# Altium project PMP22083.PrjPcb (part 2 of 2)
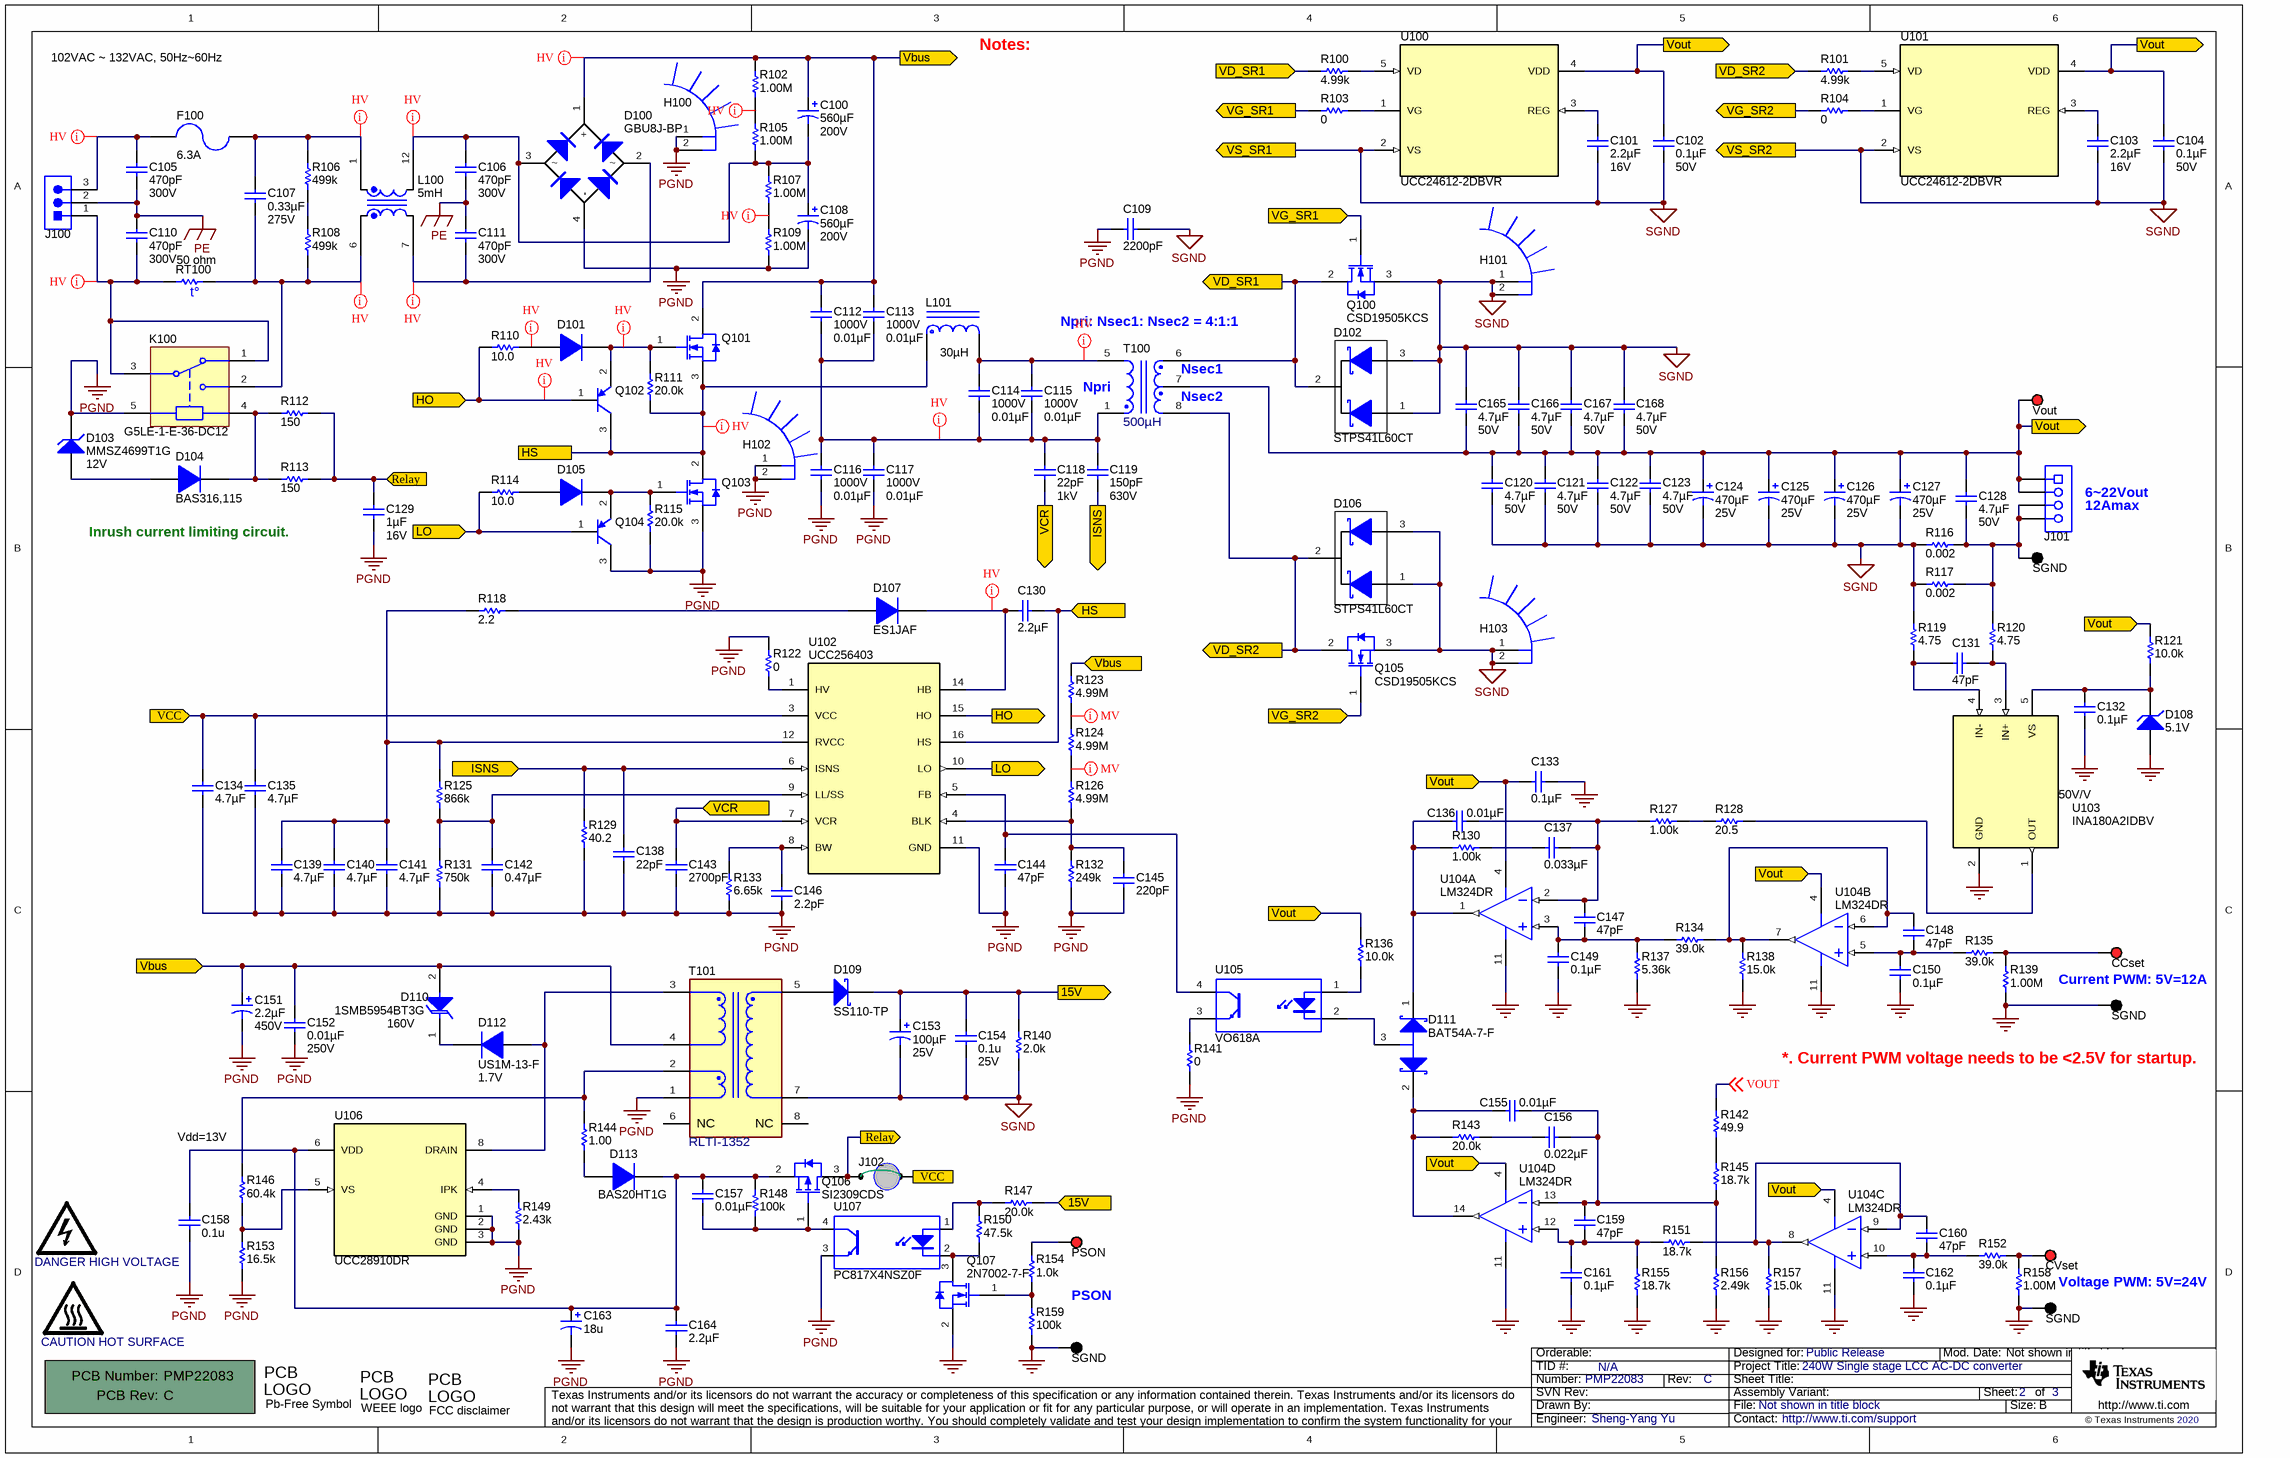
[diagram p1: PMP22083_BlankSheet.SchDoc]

## Sheet PMP22083_BlankSheet.SchDoc (continued)

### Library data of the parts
!PCB100 = CMP-0003618-2: Manufacturer: Any; PartNumber: PMP22083
C100 C108 = CMP-0010098-2: CAP, AL, 560 uF, 200 V, +/- 20%, TH; Manufacturer: Nichicon; PartNumber: LGR2D561MELZ45; TaMin_C: -25°C; Polarized: Y; SizeAreaWB_mm2: 576; Value1: Unknown; U/M: EA; Value: 560uF; TaMax_C: 85°C; SizeZ_mm: 32; SizeX_mm: 22; SizeArea_mm2: 484; CompType: Capacitor; AEC Qualified: N; AEC Category: Q200
C101 C103 = 885012106018: CAP, CERM, 2.2 µF, 16 V,+/- 20%, X5R, 0603; Manufacturer: Wurth Elektronik; Polarized: N; CompType: Capacitor; Value: 2.2uF; U/M: EA; Cap_F: 0.0000022; Tolerance_%: 20; VDC_V: 16; TaMin_C: -55; TaMax_C: 85; SizeArea_mm2: 1.28; SizeAreaWB_mm2: 4.68; SizeX_mm: 1.6; SizeY_mm: 0.8; SizeZ_mm: 1; AEC Category: Q200; Green_Lifecycle: Not Set; Green_REACh: Incomplete
C102 C104 = 885012206095: CAP, CERM, 0.1 µF, 50 V,+/- 10%, X7R, 0603; Manufacturer: Wurth Elektronik; Polarized: N; CompType: Capacitor; Value: 0.1uF; U/M: EA; Cap_F: 0.0000001; Tolerance_%: 10; VDC_V: 50; TaMin_C: -55; TaMax_C: 125; SizeArea_mm2: 1.28; SizeAreaWB_mm2: 4.68; SizeX_mm: 1.6; SizeY_mm: 0.8; SizeZ_mm: 1; AEC Category: Q200; Green_Lifecycle: Active; Green_REACh: Passed
C105 C106 C110 C111 = VY2471K29Y5SS63V7: CAP, CERM, 470pF, 300V, +/-10%, VY2, 5x7.5 mm; Manufacturer: Vishay-Bccomponents; Polarized: N; CompType: Capacitor; U/M: EA; Cap_F: 0.00000000047; Tolerance_%: 10; Value1: Unknown; VDC_V: 300; TaMin_C: -40; TaMax_C: 125; Cap_Case: Disk, 5x7.5 mm
C107 = ECQ-U2A334ML: CAP, Film, 0.33uF, 275V, +/-20%, TH; Manufacturer: Panasonic; Polarized: N; CompType: Capacitor; U/M: EA; Cap_F: 0.00000033; Tolerance_%: 20; Value1: Unknown; VDC_V: 275; TaMin_C: -40; TaMax_C: 100; Cap_Case: Radial,17.5x17.5x9.5mm
C109 = AY2222M35Y5US63L7: CAP, CERM, 2200 pF, 300 V, +/- 20%, Y5U, AEC-Q200 Grade 1, D9.5xT5mm; Manufacturer: Vishay-Bccomponents; Polarized: N; CompType: Capacitor; Value: 2200pF; U/M: EA; Cap_F: 0.0000000022; Tolerance_%: 20; Value1: Unknown; VDC_V: 300; Value2: 300V; TaMin_C: -55; TaMax_C: 125; Cap_Case: 9.5x5mm; SizeArea_mm2: 47.5; SizeAreaWB_mm2: 80.5; SizeX_mm: 9.5; SizeY_mm: 5; SizeZ_mm: 14.5; AEC Category: Q200; AEC Qualified: Y; AEC Grade: 1
C112-C117 = CMP-0074802-2: CAP FILM 10000PF 5% 1KVDC RADIAL; Manufacturer: TDK; TaMin_C: -55°C; Polarized: N; SizeAreaWB_mm2: 120.0; Value: 0.01uF; TaMax_C: 105°C; VAC: 400; SizeZ_mm: 12.0; SizeX_mm: 13.0; SizeY_mm: 6.0; Cap_Case: 13x6x12mm; SizeArea_mm2: 78.0; CompType: Capacitor; Cap_F: 22nF; AEC Category: Q200
C118 = VJ1206A220JXGAT5Z: CAP, CERM, 22 pF, 1000 V,+/- 5%, C0G/NP0, 1206; Manufacturer: Vishay-Vitramon; Polarized: N; CompType: Capacitor; Value: 22pF; U/M: EA; Cap_F: 0.000000000022; Tolerance_%: 5; VDC_V: 1000; TaMin_C: -55; TaMax_C: 125; SizeArea_mm2: 5.12; SizeAreaWB_mm2: 10.92; SizeX_mm: 3.2; SizeY_mm: 1.6; SizeZ_mm: 1.35; AEC Category: Q200
C119 = GRM31A5C2J151JW01D: CAP, CERM, 150 pF, 630 V, +/- 5%, C0G/NP0, 1206; Manufacturer: MuRata; Polarized: N; CompType: Capacitor; Value: 150pF; U/M: EA; Cap_F: 0.00000000015; Tolerance_%: 5; Value1: Unknown; VDC_V: 630; TaMin_C: -55; TaMax_C: 125; SizeArea_mm2: 5.12; SizeAreaWB_mm2: 10.92; SizeX_mm: 3.2; SizeY_mm: 1.6; SizeZ_mm: 1.35; AEC Category: Q200
C120-C123 C128 C165-C168 = UMK316AB7475KL-T: CAP, CERM, 4.7 µF, 50 V,+/- 10%, X7R, 1206; Manufacturer: Taiyo Yuden; Polarized: N; CompType: Capacitor; Value: 4.7uF; U/M: EA; Cap_F: 0.0000047; Tolerance_%: 10; VDC_V: 50; TaMin_C: -55; TaMax_C: 125; Cap_Case: 1206; SizeArea_mm2: 5.12; SizeAreaWB_mm2: 10.92; SizeX_mm: 3.2; SizeY_mm: 1.6; SizeZ_mm: 1.9; AEC Category: Q200; Green_Lifecycle: Active; Green_REACh: Passed
C124-C127 = EEU-FR1V681: CAP ALUM POLY 470UF 20% 25V T/H; Manufacturer: Panasonic; Polarized: Y; CompType: Capacitor; U/M: EA; Tolerance_%: 20; VDC_V: 25; IRMS_A: 2.47; TaMin_C: -40; TaMax_C: 105; SizeAreaWB_mm2: 144; SizeArea_mm2: 100; SizeX_mm: 10; SizeZ_mm: 22; AEC Category: Q200; AEC Qualified: N
C129 = 0805YD105KAT2A: CAP, CERM, 1uF, 16V, +/-10%, X5R, 0805; Manufacturer: AVX; Polarized: N; CompType: Capacitor; U/M: EA; Cap_F: 0.000001; Tolerance_%: 10; ESR_Ohm: 0.012; Value1: 0.012 ohm; VDC_V: 16; TaMin_C: -55; TaMax_C: 85; Cap_Case: 0805
C130 = C1206C225K4RACTU: CAP, CERM, 2.2 µF, 16 V, +/- 10%, X7R, 1206; Manufacturer: Kemet; Polarized: N; CompType: Capacitor; Value: 2.2uF; U/M: EA; Cap_F: 0.0000022; Tolerance_%: 10; ESR_ohm: 0.009; Value1: 0.009 ohm; VDC_V: 16; Value2: 16V; IRMS_A: 4.46; TaMin_C: -55; TaMax_C: 125; AEC Category: Q200; SizeArea_mm2: 5.12; SizeAreaWB_mm2: 10.92; SizeX_mm: 3.2; SizeY_mm: 1.6; SizeZ_mm: 1.35
C131 = C0603C470J5GACTU: CAP, CERM, 47 pF, 50 V, +/- 5%, C0G/NP0, 0603; Manufacturer: Kemet; Polarized: N; CompType: Capacitor; Value: 47pF; U/M: EA; Cap_F: 0.000000000047; Tolerance_%: 5; Value1: Unknown; VDC_V: 50; Value2: 50V; TaMin_C: -55; TaMax_C: 125; SizeArea_mm2: 1.28; SizeAreaWB_mm2: 4.68; SizeX_mm: 1.6; SizeY_mm: 0.8; SizeZ_mm: 1; AEC Category: Q200
C132 = GRM155R61E104KA87D: CAP, CERM, 0.1 µF, 25 V, +/- 10%, X5R, 0402; Manufacturer: MuRata; Polarized: N; CompType: Capacitor; Value: 0.1uF; U/M: EA; Cap_F: 0.0000001; Tolerance_%: 10; Value1: Unknown; VDC_V: 25; Value2: 25V; TaMin_C: -55; TaMax_C: 85
C133 = C1206C104K5RACTU: CAP, CERM, 0.1 µF, 50 V, +/- 10%, X7R, 1206; Manufacturer: Kemet; Polarized: N; CompType: Capacitor; Value: 0.1uF; U/M: EA; Cap_F: 0.0000001; Tolerance_%: 10; ESR_ohm: 0.059; Value1: 0.059 ohm; VDC_V: 50; Value2: 50V; IRMS_A: 1.2; TaMin_C: -55; TaMax_C: 125; SizeArea_mm2: 5.12; SizeAreaWB_mm2: 10.92; SizeX_mm: 3.2; SizeY_mm: 1.6; SizeZ_mm: 1.35; AEC Category: Q200
C134 C135 C139-C141 = GRM188R61C475KAAJ: CAP, CERM, 4.7 µF, 16 V, +/- 10%, X5R, 0603; Manufacturer: MuRata; Polarized: N; CompType: Capacitor; Value: 4.7uF; U/M: EA; Cap_F: 0.0000047; Tolerance_%: 10; Value1: Unknown; VDC_V: 16; Value2: 16V; TaMin_C: -55; TaMax_C: 85; AEC Category: Q200
C136 C155 = GRM155R71H103KA88D: CAP, CERM, 0.01 µF, 50 V, +/- 10%, X7R, 0402; Manufacturer: MuRata; Polarized: N; CompType: Capacitor; Value: 0.01uF; U/M: EA; Cap_F: 0.00000001; Tolerance_%: 10; Value1: Unknown; VDC_V: 50; Value2: 50V; TaMin_C: -55; TaMax_C: 125
C137 = GRM155R61C333KA01D: CAP, CERM, 0.033 µF, 16 V,+/- 10%, X5R, 0402; Manufacturer: MuRata; Polarized: N; CompType: Capacitor; Value: 0.033uF; U/M: EA; Cap_F: 0.000000033; Tolerance_%: 10; VDC_V: 16; Value2: 16V; TaMin_C: -55; TaMax_C: 85; SizeArea_mm2: 0.5; SizeAreaWB_mm2: 3; SizeX_mm: 1; SizeZ_mm: 0.6; AEC Category: Q200; Green_Lifecycle: Active; Green_REACh: Passed
C138 = 06035A220JAT2A: CAP, CERM, 22 pF, 50 V,+/- 5%, C0G/NP0, 0603; Manufacturer: AVX; Polarized: N; CompType: Capacitor; Value: 22pF; U/M: EA; Cap_F: 0.000000000022; Tolerance_%: 5; ESR_ohm: 0.259; Value1: 0.259 ohm; VDC_V: 50; Value2: 50V; TaMin_C: -55; TaMax_C: 125; SizeArea_mm2: 1.28; SizeAreaWB_mm2: 4.68; SizeX_mm: 1.6; SizeY_mm: 0.8; SizeZ_mm: 1; AEC Category: Q200; Green_Lifecycle: Active; Green_REACh: Passed
C142 = C0603C474Z8VACTU: CAP, CERM, 0.47 µF, 10 V,+80/-20%, Y5V, 0603; Manufacturer: Kemet; Polarized: N; CompType: Capacitor; Value: 0.47uF; U/M: EA; Cap_F: 0.00000047; Tolerance_%: 80; VDC_V: 10; Value2: 10V; TaMin_C: -30; TaMax_C: 85; SizeArea_mm2: 1.28; SizeAreaWB_mm2: 4.68; SizeX_mm: 1.6; SizeY_mm: 0.8; SizeZ_mm: 1; AEC Category: Q200; Green_Lifecycle: Not Set; Green_REACh: Incomplete
C143 = GRM188R71E272KA01D: CAP, CERM, 2700 pF, 25 V,+/- 10%, X7R, 0603; Manufacturer: MuRata; Polarized: N; CompType: Capacitor; Value: 2700pF; U/M: EA; Cap_F: 0.0000000027; Tolerance_%: 10; VDC_V: 25; Value2: 25V; TaMin_C: -55; TaMax_C: 125; SizeArea_mm2: 1.28; SizeAreaWB_mm2: 4.68; SizeX_mm: 1.6; SizeY_mm: 0.8; SizeZ_mm: 1; AEC Category: Q200; Green_Lifecycle: Active; Green_REACh: Passed
C144 = GRM1885C1H470FA01J: CAP, CERM, 47 pF, 50 V, +/- 1%, C0G/NP0, 0603; Manufacturer: MuRata; Polarized: N; CompType: Capacitor; Value: 47pF; U/M: EA; Cap_F: 0.000000000047; Tolerance_%: 1; Value1: Unknown; VDC_V: 50; Value2: 50V; TaMin_C: -55; TaMax_C: 125; AEC Category: Q200
C145 = GRM188R71H221KA01D: CAP, CERM, 220 pF, 50 V, +/- 10%, X7R, 0603; Manufacturer: MuRata; Polarized: N; CompType: Capacitor; Value: 220pF; U/M: EA; Cap_F: 0.00000000022; Tolerance_%: 10; Value1: Unknown; VDC_V: 50; Value2: 50V; TaMin_C: -55; TaMax_C: 125; AEC Category: Q200
C146 = 06035A2R2CAT2A: CAP, CERM, 2.2 pF, 50 V, +/- 11%, C0G/NP0, 0603; Manufacturer: AVX; Polarized: N; CompType: Capacitor; Value: 2.2pF; U/M: EA; Cap_F: 0.0000000000022; Tolerance_%: 11; ESR_ohm: 1.033; Value1: 1.033 ohm; VDC_V: 50; Value2: 50V; TaMin_C: -55; TaMax_C: 125; SizeArea_mm2: 1.28; SizeAreaWB_mm2: 4.68; SizeX_mm: 1.6; SizeY_mm: 0.8; SizeZ_mm: 1; AEC Category: Q200
C147 C148 C160 = GRM1885C1H470JA01D: CAP, CERM, 47 pF, 50 V,+/- 5%, C0G/NP0, 0603; Manufacturer: MuRata; Polarized: N; CompType: Capacitor; Value: 47pF; U/M: EA; Cap_F: 0.000000000047; Tolerance_%: 5; VDC_V: 50; Value2: 50V; TaMin_C: -55; TaMax_C: 125; SizeArea_mm2: 1.28; SizeAreaWB_mm2: 4.68; SizeX_mm: 1.6; SizeY_mm: 0.8; SizeZ_mm: 1; AEC Category: Q200; Green_Lifecycle: Active; Green_REACh: Passed
C149 C150 = 08053C104JAT2A: CAP, CERM, 0.1 µF, 25 V,+/- 5%, X7R, 0805; Manufacturer: AVX; Polarized: N; CompType: Capacitor; Value: 0.1uF; U/M: EA; Cap_F: 0.0000001; Tolerance_%: 5; VDC_V: 25; Value2: 25V; TaMin_C: -55; TaMax_C: 125; Cap_Case: 0805; SizeArea_mm2: 2.5; SizeAreaWB_mm2: 6.75; SizeX_mm: 2; SizeY_mm: 1.25; SizeZ_mm: 1.45; AEC Category: Q200
C151 = 225CKE450MJM: CAP, AL, 2.2 µF, 450 V, +/- 20%, 150.71 ohm, TH; Manufacturer: Illinois Capacitor; Polarized: Y; CompType: Capacitor; Value: 2.2uF; U/M: EA; Cap_F: 0.0000022; Tolerance_%: 20; VDC_V: 450; ESR_ohm: 150.71; IRMS_A: 0.03; TaMin_C: -25; TaMax_C: 105; Cap_Case: 8x11.5mm; SizeAreaWB_mm2: 100; SizeArea_mm2: 64; SizeX_mm: 8; SizeZ_mm: 13; AEC Category: Q200; AEC Qualified: N; Green_Lifecycle: Not Set; Green_REACh: Incomplete
C152 = C1206C103KARACTU: CAP, CERM, 0.01 µF, 250 V,+/- 10%, X7R, 1206; Manufacturer: Kemet; Polarized: N; CompType: Capacitor; Value: 0.01uF; U/M: EA; Cap_F: 0.00000001; Tolerance_%: 10; VDC_V: 250; TaMin_C: -55; TaMax_C: 125; SizeArea_mm2: 5.12; SizeAreaWB_mm2: 10.92; SizeX_mm: 3.2; SizeY_mm: 1.6; SizeZ_mm: 1.35; AEC Category: Q200; Green_Lifecycle: Active; Green_REACh: Passed
C153 = ECA-1EHG101: CAP, AL, 100 µF, 25 V, +/- 20%, TH; Manufacturer: Panasonic; Polarized: Y; CompType: Capacitor; Value: 100uF; U/M: EA; Cap_F: 0.0001; Tolerance_%: 20; VDC_V: 25; IRMS_A: 0.13; TaMin_C: -55; TaMax_C: 105; Cap_Case: 6.3x11.2mm; SizeAreaWB_mm2: 68.89; SizeArea_mm2: 39.69; SizeX_mm: 6.3; SizeZ_mm: 11.2; AEC Category: Q200; AEC Qualified: N
C154 = 08053C104KAT2A: CAP, CERM, 0.1uF, 25V, +/-10%, X7R, 0805; Manufacturer: AVX; Polarized: N; CompType: Capacitor; U/M: EA; Cap_F: 0.0000001; Tolerance_%: 10; ESR_Ohm: 0.28; Value1: 0.28 ohm; VDC_V: 25; TaMin_C: -55; TaMax_C: 125; Cap_Case: 0805
C156 = GCM155R71H223KA55D: CAP, CERM, 0.022 µF, 50 V,+/- 10%, C0G/NP0, 0402; Manufacturer: MuRata; Polarized: N; CompType: Capacitor; Value: 0.022uF; U/M: EA; Cap_F: 0.000000022; Tolerance_%: 10; VDC_V: 50; Value2: 50V; TaMin_C: -55; TaMax_C: 125; SizeArea_mm2: 0.5; SizeAreaWB_mm2: 3; SizeX_mm: 1; SizeZ_mm: 0.6; AEC Category: Q200
C157 = 885012206040: CAP, CERM, 0.01 µF, 16 V,+/- 10%, X7R, 0603; Manufacturer: Wurth Elektronik; Polarized: N; CompType: Capacitor; Value: 0.01uF; U/M: EA; Cap_F: 0.00000001; Tolerance_%: 10; VDC_V: 16; Value2: 16V; TaMin_C: -55; TaMax_C: 125; SizeArea_mm2: 1.28; SizeAreaWB_mm2: 4.68; SizeX_mm: 1.6; SizeY_mm: 0.8; SizeZ_mm: 1; AEC Category: Q200; Green_Lifecycle: Active; Green_REACh: Passed
C158 = 06035C104KAT2A: CAP, CERM, 0.1uF, 50V, +/-10%, X7R, 0603; Manufacturer: AVX; Polarized: N; CompType: Capacitor; U/M: EA; Cap_F: 0.0000001; Tolerance_%: 10; Value1: Unknown; VDC_V: 50; TaMin_C: -55; TaMax_C: 125
C159 = GRM1555C1H470JA01D: CAP, CERM, 47 pF, 50 V,+/- 5%, C0G/NP0, 0402; Manufacturer: MuRata; Polarized: N; CompType: Capacitor; Value: 47pF; U/M: EA; Cap_F: 0.000000000047; Tolerance_%: 5; VDC_V: 50; Value2: 50V; TaMin_C: -55; TaMax_C: 125; SizeArea_mm2: 0.5; SizeAreaWB_mm2: 3; SizeX_mm: 1; SizeZ_mm: 0.6; AEC Category: Q200; Green_Lifecycle: Active; Green_REACh: Passed
C161 C162 = 06035C104KAT2A: CAP, CERM, 0.1 µF, 50 V,+/- 10%, X7R, 0603; Manufacturer: AVX; Polarized: N; CompType: Capacitor; Value: 0.1uF; U/M: EA; Cap_F: 0.0000001; Tolerance_%: 10; VDC_V: 50; Value2: 50V; TaMin_C: -55; TaMax_C: 125; SizeArea_mm2: 1.28; SizeAreaWB_mm2: 4.68; SizeX_mm: 1.6; SizeY_mm: 0.8; SizeZ_mm: 1; AEC Category: Q200; Green_Lifecycle: Active; Green_REACh: Passed
C163 = 25ML22MEFC5X5: CAP, AL, 18uF, 35V, +/-20%, TH; Manufacturer: Rubycon; Polarized: Y; CompType: Capacitor; U/M: EA; Cap_F: 0.000022; Tolerance_%: 20; Value1: Unknown; VDC_V: 35; TaMin_C: -40; TaMax_C: 105; Cap_Case: 5x5
C164 = GRM188R6YA225KA12D: CAP, CERM, 2.2 µF, 35 V, +/- 10%, X5R, 0603; Manufacturer: MuRata; Polarized: N; CompType: Capacitor; Value: 2.2uF; U/M: EA; Cap_F: 0.0000022; Tolerance_%: 10; Value1: Unknown; VDC_V: 35; Value2: 35V; TaMin_C: -55; TaMax_C: 85; AEC Category: Q200
CCset CVset PSON Vout = 5000: Test Point, Miniature, Red, TH; Manufacturer: Keystone; CompType: Test Point Loop; ContactFinish: Silver; Green_Lifecycle: Active; Green_REACh: Passed
D100 = GBU8J-BP: Diode, Switching-Bridge, 420V, 8A, TH; Manufacturer: Micro Commercial Components; U/M: EA; Vf_V: 1; Value2: 1V; Io_A: 8; Vr_V: 420; TJmax_C: 175
D101 D105 = MMDL914-TP: Diode, Switching, 100 V, 0.2 A, SOD-323; Manufacturer: Micro Commercial Components; U/M: EA; Vf_V: 1; Value: 100V; Value1: 0.2A; Value2: 1V; Io_A: 0.2; Vr_V: 100; TJmax_C: 150; SizeAreaWB_mm2: 8.695; SizeArea_mm2: 3.645; SizeX_mm: 2.7; SizeY_mm: 1.35; AEC Category: Q101
D102 D106 = STPS41H100CTY: DIODE ARRAY SCHOTTKY 60V TO220AB; Manufacturer: STMicroelectronics; SymbolCreator: a0411947; U/M: EA; Value1: 20A; Io_A: 20; TJmax_C: 175; SizeAreaWB_mm2: 79.3; SizeArea_mm2: 45.9; SizeX_mm: 10.2; SizeY_mm: 4.5; SizeZ_mm: 19.4; AEC Category: Q101; AEC Qualified: Y; Green_Lifecycle: Not Set; Green_REACh: Incomplete
D103 = MMSZ4699T1G: Diode, Zener, 12 V, 500 mW, SOD-123; Manufacturer: ON Semiconductor; SymbolCreator: a0412235; U/M: EA; Power_W: 0.5; Vz_V: 12; Value1: 0.5W; RJA_CperW: 340
D104 = BAS316,115: Diode, Ultrafast, 100 V, 0.25 A, SOD-323; Manufacturer: NXP Semiconductor; U/M: EA; Vf_V: 1.4; Value: 100V; Value1: 0.25A; Value2: 1.4V; Io_A: 0.25; Vr_V: 100; TJmax_C: 150
D107 = ES1JAF: Diode, Ultrafast, 600 V, 1 A, AEC-Q101, SMAF; Manufacturer: Fairchild Semiconductor; U/M: EA; Vf_V: 1.7; Value: 600V; Value1: 1A; Value2: 1.7V; Io_A: 1; Vr_V: 600; TJmax_C: 150; AEC Category: Q101; AEC Qualified: Y
D108 = MMSZ5231BS-7-F: Diode, Zener, 5.1 V, 200 mW, SOD-323; Manufacturer: Diodes Inc.; SymbolCreator: a0412235; U/M: EA; Power_W: 0.2; Vz_V: 5.1; Value1: 0.2W; RJA_CperW: 350; SizeAreaWB_mm2: 8.695; SizeArea_mm2: 3.645; SizeX_mm: 2.7; SizeY_mm: 1.35; SizeZ_mm: 1; AEC Category: Q101
D109 = SS110-TP: Diode, Schottky, 100 V, 1 A, SMA; Manufacturer: Micro Commercial Components; U/M: EA; Vf_V: 0.85; Value: 100V; Value1: 1A; Value2: 0.85V; Io_A: 1; Vr_V: 100; TJmax_C: 125; SizeAreaWB_mm2: 37.3428; SizeArea_mm2: 16.3228; SizeX_mm: 5.59; SizeY_mm: 2.92; SizeZ_mm: 2.87; AEC Category: Q101; AEC Qualified: N; Green_Lifecycle: Not Set; Green_REACh: Incomplete
D110 = SMBJ120A-13-F: Diode, TVS, Uni, 160V, 3W, SMB; Manufacturer: Diodes Inc.; U/M: EA; Power_W: 5; Vr_V: 160
D111 = BAT54A-7-F: Diode, Schottky, 30 V, 0.2 A, SOT-23; Manufacturer: Diodes Inc.; U/M: EA; Vf_V: 0.65; Value: 30V; Value1: 0.2A; Value2: 0.65V; Io_A: 0.2; Vr_V: 30; TJmax_C: 125; SizeAreaWB_mm2: 14; SizeArea_mm2: 7.5; SizeX_mm: 2.5; SizeY_mm: 3; SizeZ_mm: 1.1; AEC Category: Q101
D112 = US1M-13-F: Diode, Ultrafast, 1000V, 1A, SMA; Manufacturer: Diodes Inc.; U/M: EA; Vf_V: 1.7; Io_A: 1; Vr_V: 1000; TJmax_C: 150; RJC_CperW: 30
D113 = BAS316,115: DIODE SWITCH 200V 200MA SOD323; U/M: EA; Vf_V: 1.4; Value1: 0.25A; Vr_V: 100; Value2: 100V; TJmax_C: 150; Type: Ultrafast
F100 = 37216300001: Fuse, 6.3 A, 250VAC/VDC, TH; Manufacturer: Littelfuse; VDC_V: 250
H100 = 532602B02500G: Heatsink, TO-220 Vertical; Manufacturer: Aavid; SymbolCreator: a0799628
H101-H103 = 531202B02500G: HEATSINK TO-220 W/PINS 2" TALL; Manufacturer: Aavid; SymbolCreator: a0799628; Note: footprint renamed from HSINK_531202B025B025 to 531202
J100 = CMP-0054856-1: Header, 312mil, 3x1, Tin, TH; Manufacturer: TE Connectivity; CT: FALSE
J101 = ED120/4DS: Terminal Block, 5.08 mm, 4x1, Brass, TH; Manufacturer: On-Shore Technology; SymbolCreator: a0411947; Pitch_mm: 5.08; Gender: Female; Shrouded: N; Row_Count: 1; Current_A: 15; Voltage_V: 300; Cert_CULUS: Y
J102 = CMP-0055441-1: Jumper Wire, 500mil spacing, Green, pkg of 200; Manufacturer: 3M; CNHeader: FALSE; Green_Lifecycle: Active; Green_REACh: Passed
K100 = 875B-1CC-F-S-12VDC: Relay, SPDT ( 1 Form C), 16A, 12 VDC, TH; Manufacturer: Omron; SymbolCreator: Altium; Coil Current: 30 mA; Coil Power: 360 mW; Coil Resistance: 400 ohms; Coil Voltage: 12 VDC; Turn Off Voltage (Min): 0.6 VDC; Turn On Voltage (Max): 9 VDC; Time Operate (s): 0.015; Time Release (s): 0.01
L100 = 744825510: Coupled inductor, 5 mH, 6A, TH; Manufacturer: Wurth Elektronik; SymbolCreator: a0799628; Value: 5mH; AEC Category: Q200
L101 = CMP-0086704-1: 30uH & 8A INDUCTOR; Manufacturer: Payton Planar; AEC Qualified: No; SizeZ_mm: 23mm; Symbol Name: SYM-61219
LOGO100 = CMP-0074835-1: IEC 61010-1 High Voltage Warning; Library Reference: IEC_HighVoltage; SymbolCreator: a0412235
LOGO101 = CMP-0074837-1: IEC 61010-1 Hot Surface Warning; Library Reference: IEC_HotSurface; SymbolCreator: a0412235
Logo102 = Pb-Free: SymbolCreator: a0412235
Logo103 = CMP-0074769-1
Logo104 = CMP-0074847-1: FCC_disclaimer; Library Reference: Logo
Q100 Q105 = CSD19505KCS: MOSFET, N-CH, 80 V, 150 A, KCS0003B (TO-220-3); Manufacturer: Texas Instruments; Alternate Manufacturer: None; U/M: EA; ChType: N; Value: 80V; VdsMax_V: 80; Value1: ? ohm; Value2: 76 nC; QgTyp_nC: 76; Vgs_V: 20; IdsMax_A: 150; SizeAreaWB_mm2: 79.648; SizeArea_mm2: 46.228; SizeX_mm: 4.55; SizeY_mm: 10.16; SizeZ_mm: 20.45; AEC Category: Q101
Q101 Q103 = IPA65R190CFD: N-Channel 600V 25A (Tc) 125W (Tc) Through Hole PG-TO220-3; Manufacturer: Infineon Technologies; Alternate Manufacturer: None; CompType: MOSFET; U/M: EA; ChType: N; Value: 650V; VdsMax_V: 650; Value1: ? ohm; Value2: 68 nC; QgTyp_nC: 68; Vgs_V: 20; IdsMax_A: 17.5; SizeAreaWB_mm2: 79.3; SizeArea_mm2: 45.9; SizeX_mm: 10.2; SizeY_mm: 4.5; AEC Category: Q101
Q102 Q104 = FMMT718TA, Diodes Inc.: Transistor, PNP, 20 V, 1.5 A, SOT-23; CompType: BJT; PNP: 1; NPN: 0; Vceo_V: 20; Value: 20 V; IcRated_A: 1.5; Value1: 1.5 A; HfeMax: 6; TaMin_C: -55; TaMax_C: 150; SizeAreaWB_mm2: 14; SizeArea_mm2: 7.5; SizeX_mm: 2.5; SizeY_mm: 3; SizeZ_mm: 1.1; U/M: EA; AEC Category: Q101
Q106 = SI2309CDS-T1-E3: MOSFET, P-CH, -60 V, -1.6 A, SOT-23; Manufacturer: Vishay-Siliconix; Alternate Manufacturer: None; U/M: EA; ChType: P; Value: -60V; Value1: 0.45 ohm; Rdson45_ohm: 0.45; Value2: 2.7 nC; QgTyp_nC: 2.7; Vgs_V: -20; SizeAreaWB_mm2: 14; SizeArea_mm2: 7.5; SizeX_mm: 2.5; SizeY_mm: 3; SizeZ_mm: 1.1; AEC Category: Q101; Green_Lifecycle: Active; Green_REACh: Passed
Q107 = 2N7002-7-F: MOSFET, N-CH, 60 V, 0.17 A, SOT-23; Manufacturer: Diodes Inc.; Alternate Manufacturer: None; U/M: EA; ChType: N; Value: 60V; VdsMax_V: 60; Value1: 7.5 ohm; Rdson45_ohm: 7.5; Value2: 223 nC; QgTyp_nC: 223; Vgs_V: 20; IdsMax_A: 0.17
R100 R101 = CRCW12064K99FKEA: RES, 4.99 k, 1%, 0.25 W, 1206; Manufacturer: Vishay-Dale; CompType: Resistor; Value: 4.99k; Res_ohm: 4990; Value_Code: 4k99; Tolerance_%: 1; Power_W: 0.25; Value2: 0.25W; VDC_V: 200; TempCo: 100 ppm/C; SizeArea_mm2: 5.12; SizeX_mm: 3.2; SizeY_mm: 1.6; SizeZ_mm: 1.35; EIA_Code: E96; U/M: EA; AEC Category: Q200; Green_Lifecycle: Active; Green_REACh: Passed
R102 R105 R107 R109 = CRCW12061M00FKEA: RES, 1.00 M, 1%, 0.25 W, 1206; Manufacturer: Vishay-Dale; CompType: Resistor; Value: 1.00Meg; Res_ohm: 1000000; Value_Code: 1M00; Tolerance_%: 1; Power_W: 0.25; Value2: 0.25W; VDC_V: 200; TempCo: 100 ppm/C; SizeArea_mm2: 5.12; SizeX_mm: 3.2; SizeY_mm: 1.6; SizeZ_mm: 1.35; EIA_Code: E96; U/M: EA; AEC Category: Q200; Green_Lifecycle: Active; Green_REACh: Passed
R103 R104 = CRCW04020000Z0ED: RES, 0, 5%, 0.063 W, 0402; Manufacturer: Vishay-Dale; CompType: Resistor; Value: 0; Value_Code: 0000; Tolerance_%: 5; Power_W: 0.063; Value2: 0.063W; VDC_V: 50; TempCo: 200 ppm/C; SizeArea_mm2: 0.5; SizeX_mm: 1; SizeZ_mm: 0.6; EIA_Code: E24; U/M: EA; AEC Category: Q200; Green_Lifecycle: Active; Green_REACh: Passed
R106 R108 = CRCW1206499KFKEA: RES, 499 k, 1%, 0.25 W, 1206; Manufacturer: Vishay-Dale; CompType: Resistor; Value: 499k; Res_ohm: 499000; Tolerance_%: 1; Power_W: 0.25; Value2: 0.25W; VDC_V: 200; TempCo: 100 ppm/C; SizeArea_mm2: 5.12; SizeX_mm: 3.2; SizeY_mm: 1.6; SizeZ_mm: 1.35; EIA_Code: E96; U/M: EA; AEC Category: Q200; Green_Lifecycle: Active; Green_REACh: Passed
R110 R114 = CRCW060310R0FKEA: RES, 10.0, 1%, 0.1 W, 0603; Manufacturer: Vishay-Dale; CompType: Resistor; Value: 10.0; Res_ohm: 10; Value_Code: 10R0; Tolerance_%: 1; Power_W: 0.1; Value2: 0.1W; VDC_V: 75; TempCo: 100 ppm/C; SizeArea_mm2: 1.28; SizeX_mm: 1.6; SizeY_mm: 0.8; EIA_Code: E96; U/M: EA; AEC Category: Q200; Green_Lifecycle: Active; Green_REACh: Passed
R111 R115 = CRCW060320K0FKEA: RES, 20.0 k, 1%, 0.1 W, 0603; Manufacturer: Vishay-Dale; CompType: Resistor; Value: 20.0k; Res_ohm: 20000; Value_Code: 20k0; Tolerance_%: 1; Power_W: 0.1; Value2: 0.1W; VDC_V: 75; TempCo: 100 ppm/C; SizeArea_mm2: 1.28; SizeX_mm: 1.6; SizeY_mm: 0.8; EIA_Code: E96; U/M: EA; AEC Category: Q200; Green_Lifecycle: Active; Green_REACh: Passed
R112 R113 = CRCW1206150RJNEA: RES, 150, 5%, 0.25 W, 1206; Manufacturer: Vishay-Dale; CompType: Resistor; Value: 150; Value_Code: 150R; Tolerance_%: 5; Power_W: 0.25; Value2: 0.25W; VDC_V: 200; TempCo: 200 ppm/C; EIA_Code: E24; U/M: EA
R116 R117 = PMR50HZPFV2L00: RES, 0.002, 1%, 1 W, 2010; Manufacturer: Rohm; CompType: Resistor; Value: 0.002; Value_Code: 2L000; Tolerance_%: 1; Value2: 1W; TempCo: 100 ppm/C; SizeArea_mm2: 12.5; SizeX_mm: 5; SizeY_mm: 2.5; SizeZ_mm: 1.66; U/M: EA; AEC Category: Q200
R118 = CRCW06032R20JNEA: RES, 2.2, 5%, 0.1 W, 0603; Manufacturer: Vishay-Dale; CompType: Resistor; Value: 2.2; Value_Code: 2R20; Tolerance_%: 5; Power_W: 0.1; Value2: 0.1W; VDC_V: 75; TempCo: 200 ppm/C; EIA_Code: E24; U/M: EA
R119 R120 = RC0603FR-074R75L: RES, 4.75, 1%, 0.1 W, 0603; Manufacturer: Yageo America; CompType: Resistor; Value: 4.75; Value_Code: 4R75; Tolerance_%: 1; Power_W: 0.1; Value2: 0.1W; VDC_V: 150; TempCo: 200 ppm/C; SizeArea_mm2: 1.28; SizeX_mm: 1.6; SizeY_mm: 0.8; EIA_Code: E96; U/M: EA; AEC Category: Q200
R121 = CRCW060310K0FKEA: RES, 10.0 k, 1%, 0.1 W, 0603; Manufacturer: Vishay-Dale; CompType: Resistor; Value: 10.0k; Res_ohm: 10000; Value_Code: 10k0; Tolerance_%: 1; Power_W: 0.1; Value2: 0.1W; VDC_V: 75; TempCo: 100 ppm/C; SizeArea_mm2: 1.28; SizeX_mm: 1.6; SizeY_mm: 0.8; EIA_Code: E96; U/M: EA; AEC Category: Q200
R122 = CRCW06030000Z0EA: RES, 0, 5%, 0.1 W, 0603; Manufacturer: Vishay-Dale; CompType: Resistor; Value: 0; Value_Code: 0000; Tolerance_%: 5; Power_W: 0.1; Value2: 0.1W; VDC_V: 75; TempCo: 200 ppm/C; SizeArea_mm2: 1.28; SizeX_mm: 1.6; SizeY_mm: 0.8; SizeZ_mm: 1; EIA_Code: E24; U/M: EA; AEC Category: Q200; Green_Lifecycle: Active; Green_REACh: Passed
R123 R124 R126 = CRCW12064M99FKEA: RES, 4.99 M, 1%, 0.25 W, 1206; Manufacturer: Vishay-Dale; CompType: Resistor; Value: 4.99Meg; Res_ohm: 4990000; Value_Code: 4M99; Tolerance_%: 1; Power_W: 0.25; Value2: 0.25W; VDC_V: 200; TempCo: 100 ppm/C; EIA_Code: E96; U/M: EA; AEC Category: Q200; SizeArea_mm2: 5.12; SizeX_mm: 3.2; SizeY_mm: 1.6; SizeZ_mm: 1.35
R125 = CRCW1206866KFKEA: RES, 866 k, 1%, 0.25 W, 1206; Manufacturer: Vishay-Dale; CompType: Resistor; Value: 866k; Res_ohm: 866000; Tolerance_%: 1; Power_W: 0.25; Value2: 0.25W; VDC_V: 200; TempCo: 100 ppm/C; SizeArea_mm2: 5.12; SizeX_mm: 3.2; SizeY_mm: 1.6; SizeZ_mm: 1.35; EIA_Code: E96; U/M: EA; AEC Category: Q200
R127 = CRCW12061K00FKEA: RES, 1.00 k, 1%, 0.25 W, 1206; Manufacturer: Vishay-Dale; CompType: Resistor; Value: 1.00k; Res_ohm: 1000; Value_Code: 1k00; Tolerance_%: 1; Power_W: 0.25; Value2: 0.25W; VDC_V: 200; TempCo: 100 ppm/C; SizeArea_mm2: 5.12; SizeX_mm: 3.2; SizeY_mm: 1.6; SizeZ_mm: 1.35; EIA_Code: E96; U/M: EA; AEC Category: Q200; Green_Lifecycle: Active; Green_REACh: Passed
R128 = CRCW120620R5FKEA: RES, 20.5, 1%, 0.25 W, 1206; Manufacturer: Vishay-Dale; CompType: Resistor; Value: 20.5; Value_Code: 20R5; Tolerance_%: 1; Power_W: 0.25; Value2: 0.25W; VDC_V: 200; TempCo: 100 ppm/C; SizeArea_mm2: 5.12; SizeX_mm: 3.2; SizeY_mm: 1.6; SizeZ_mm: 1.35; EIA_Code: E96; U/M: EA; AEC Category: Q200
R129 = CRCW060340R2FKEA: RES, 40.2, 1%, 0.1 W, 0603; Manufacturer: Vishay-Dale; CompType: Resistor; Value: 40.2; Value_Code: 40R2; Tolerance_%: 1; Power_W: 0.1; Value2: 0.1W; VDC_V: 75; TempCo: 100 ppm/C; SizeArea_mm2: 1.28; SizeX_mm: 1.6; SizeY_mm: 0.8; EIA_Code: E96; U/M: EA; AEC Category: Q200; Green_Lifecycle: Active; Green_REACh: Passed
R130 = CRCW04021K00FKED: RES, 1.00 k, 1%, 0.063 W, 0402; Manufacturer: Vishay-Dale; CompType: Resistor; Value: 1.00k; Res_ohm: 1000; Value_Code: 1k00; Tolerance_%: 1; Power_W: 0.063; Value2: 0.063W; VDC_V: 50; TempCo: 100 ppm/C; SizeArea_mm2: 0.5; SizeZ_mm: 0.6; EIA_Code: E96; U/M: EA; AEC Category: Q200; Green_Lifecycle: Active; Green_REACh: Passed
R131 = CRCW0603750KFKEA: RES, 750 k, 1%, 0.1 W, 0603; Manufacturer: Vishay-Dale; CompType: Resistor; Value: 750k; Res_ohm: 750000; Tolerance_%: 1; Power_W: 0.1; Value2: 0.1W; VDC_V: 75; TempCo: 100 ppm/C; SizeArea_mm2: 1.28; SizeX_mm: 1.6; SizeY_mm: 0.8; EIA_Code: E96; U/M: EA; AEC Category: Q200; Green_Lifecycle: Active; Green_REACh: Passed
R132 = CRCW0603249KFKEA: RES, 249 k, 1%, 0.1 W, 0603; Manufacturer: Vishay-Dale; CompType: Resistor; Value: 249k; Res_ohm: 249000; Tolerance_%: 1; Power_W: 0.1; Value2: 0.1W; VDC_V: 75; TempCo: 100 ppm/C; SizeArea_mm2: 1.28; SizeX_mm: 1.6; SizeY_mm: 0.8; EIA_Code: E96; U/M: EA; AEC Category: Q200; Green_Lifecycle: Active; Green_REACh: Passed
R133 = CRCW06036K65FKEA: RES, 6.65 k, 1%, 0.1 W, 0603; Manufacturer: Vishay-Dale; CompType: Resistor; Value: 6.65k; Res_ohm: 6650; Value_Code: 6k65; Tolerance_%: 1; Power_W: 0.1; Value2: 0.1W; VDC_V: 75; TempCo: 100 ppm/C; SizeArea_mm2: 1.28; SizeX_mm: 1.6; SizeY_mm: 0.8; EIA_Code: E96; U/M: EA; AEC Category: Q200
R134 R135 = RC0603FR-0739KL: RES, 39.0 k, 1%, 0.1 W, 0603; Manufacturer: Yageo America; CompType: Resistor; Value: 39.0k; Res_ohm: 39000; Value_Code: 39k0; Tolerance_%: 1; Power_W: 0.1; Value2: 0.1W; VDC_V: 150; TempCo: 200 ppm/C; SizeArea_mm2: 1.28; SizeX_mm: 1.6; SizeY_mm: 0.8; U/M: EA; AEC Category: Q200; Green_Lifecycle: Active; Green_REACh: Passed
R136 = CRCW080510K0FKEA: RES, 10.0 k, 1%, 0.125 W, 0805; Manufacturer: Vishay-Dale; CompType: Resistor; Value: 10.0k; Res_ohm: 10000; Value_Code: 10k0; Tolerance_%: 1; Power_W: 0.125; Value2: 0.125W; VDC_V: 150; TempCo: 100 ppm/C; SizeArea_mm2: 2.5; SizeX_mm: 2; SizeY_mm: 1.25; SizeZ_mm: 1.45; EIA_Code: E96; U/M: EA; AEC Category: Q200; Green_Lifecycle: Active; Green_REACh: Passed
R137 = CRCW06035K36FKEA: RES, 5.36 k, 1%, 0.1 W, 0603; Manufacturer: Vishay-Dale; CompType: Resistor; Value: 5.36k; Res_ohm: 5360; Value_Code: 5k36; Tolerance_%: 1; Power_W: 0.1; Value2: 0.1W; VDC_V: 75; TempCo: 100 ppm/C; SizeArea_mm2: 1.28; SizeX_mm: 1.6; SizeY_mm: 0.8; EIA_Code: E96; U/M: EA; AEC Category: Q200; Green_Lifecycle: Active; Green_REACh: Passed
R138 R157 = CRCW060315K0FKEA: RES, 15.0 k, 1%, 0.1 W, 0603; Manufacturer: Vishay-Dale; CompType: Resistor; Value: 15.0k; Res_ohm: 15000; Value_Code: 15k0; Tolerance_%: 1; Power_W: 0.1; Value2: 0.1W; VDC_V: 75; TempCo: 100 ppm/C; SizeArea_mm2: 1.28; SizeX_mm: 1.6; SizeY_mm: 0.8; EIA_Code: E96; U/M: EA; AEC Category: Q200; Green_Lifecycle: Active; Green_REACh: Passed
R139 R158 = CRCW06031M00FKEA: RES, 1.00 M, 1%, 0.1 W, 0603; Manufacturer: Vishay-Dale; CompType: Resistor; Value: 1.00Meg; Res_ohm: 1000000; Value_Code: 1M00; Tolerance_%: 1; Power_W: 0.1; Value2: 0.1W; VDC_V: 75; TempCo: 100 ppm/C; SizeArea_mm2: 1.28; SizeX_mm: 1.6; SizeY_mm: 0.8; EIA_Code: E96; U/M: EA; AEC Category: Q200; Green_Lifecycle: Active; Green_REACh: Passed
R140 = CRCW06032K00JNEA: RES, 2.0k ohm, 5%, 0.1W, 0603; Manufacturer: Vishay-Dale; CompType: Resistor; Res_ohm: 2000; Value_Code: 2k00; Tolerance_%: 5; Power_W: 0.1; VDC_V: 75; TempCo: 200 ppm/C; EIA_Code: E24; U/M: EA
R141 = CRCW12060000Z0EA: RES, 0, 5%, 0.25 W, 1206; Manufacturer: Vishay-Dale; CompType: Resistor; Value: 0; Value_Code: 0000; Tolerance_%: 5; Power_W: 0.25; Value2: 0.25W; VDC_V: 200; TempCo: 200 ppm/C; SizeArea_mm2: 5.12; SizeX_mm: 3.2; SizeY_mm: 1.6; SizeZ_mm: 1.35; EIA_Code: E24; U/M: EA; AEC Category: Q200; Green_Lifecycle: Active; Green_REACh: Passed
R142 = RC1206FR-0749R9L: RES, 49.9, 1%, 0.25 W, 1206; Manufacturer: Yageo America; CompType: Resistor; Value: 49.9; Value_Code: 49R9; Tolerance_%: 1; Power_W: 0.25; Value2: 0.25W; VDC_V: 200; TempCo: 100 ppm/C; SizeArea_mm2: 5.12; SizeX_mm: 3.2; SizeY_mm: 1.6; SizeZ_mm: 1.35; EIA_Code: E96; U/M: EA; AEC Category: Q200; Green_Lifecycle: Active; Green_REACh: Passed
R143 = CRCW040220K0FKED: RES, 20.0 k, 1%, 0.063 W, 0402; Manufacturer: Vishay-Dale; CompType: Resistor; Value: 20.0k; Res_ohm: 20000; Value_Code: 20k0; Tolerance_%: 1; Power_W: 0.063; Value2: 0.063W; VDC_V: 50; TempCo: 100 ppm/C; SizeArea_mm2: 0.5; SizeZ_mm: 0.6; EIA_Code: E96; U/M: EA; AEC Category: Q200; Green_Lifecycle: Active; Green_REACh: Passed
R144 = RC0603FR-071RL: RES, 1.00 ohm, 1%, 0.1W, 0603; Manufacturer: Yageo America; CompType: Resistor; Res_ohm: 1; Value_Code: 1R00; Power_W: 0.1; VDC_V: 150; TempCo: 200 ppm/C; EIA_Code: E96; U/M: EA
R145 R151 R155 = CRCW060318K7FKEA: RES, 18.7 k, 1%, 0.1 W, 0603; Manufacturer: Vishay-Dale; CompType: Resistor; Value: 18.7k; Res_ohm: 18700; Value_Code: 18k7; Tolerance_%: 1; Power_W: 0.1; Value2: 0.1W; VDC_V: 75; TempCo: 100 ppm/C; SizeArea_mm2: 1.28; SizeX_mm: 1.6; SizeY_mm: 0.8; EIA_Code: E96; U/M: EA; AEC Category: Q200; Green_Lifecycle: Active; Green_REACh: Passed
R146 = CRCW060360K4FKEA: RES, 60.4k ohm, 1%, 0.1W, 0603; Manufacturer: Vishay-Dale; CompType: Resistor; Res_ohm: 60400; Value_Code: 60k4; Tolerance_%: 1; Power_W: 0.1; VDC_V: 75; TempCo: 100 ppm/C; EIA_Code: E96; U/M: EA
R147 = CRCW120620K0FKEA: RES, 20.0 k, 1%, 0.25 W, 1206; Manufacturer: Vishay-Dale; CompType: Resistor; Value: 20.0k; Res_ohm: 20000; Value_Code: 20k0; Tolerance_%: 1; Power_W: 0.25; Value2: 0.25W; VDC_V: 200; TempCo: 100 ppm/C; SizeArea_mm2: 5.12; SizeX_mm: 3.2; SizeY_mm: 1.6; SizeZ_mm: 1.35; EIA_Code: E96; U/M: EA; AEC Category: Q200; Green_Lifecycle: Active; Green_REACh: Passed
R148 = CRCW0603100KFKEA: RES, 100 k, 1%, 0.1 W, 0603; Manufacturer: Vishay-Dale; CompType: Resistor; Value: 100k; Res_ohm: 100000; Tolerance_%: 1; Power_W: 0.1; Value2: 0.1W; VDC_V: 75; TempCo: 100 ppm/C; SizeArea_mm2: 1.28; SizeX_mm: 1.6; SizeY_mm: 0.8; EIA_Code: E96; U/M: EA; AEC Category: Q200; Green_Lifecycle: Active; Green_REACh: Passed
R149 = CRCW06032K43FKEA: RES, 2.43k ohm, 1%, 0.1W, 0603; Manufacturer: Vishay-Dale; CompType: Resistor; Res_ohm: 2430; Value_Code: 2k43; Tolerance_%: 1; Power_W: 0.1; VDC_V: 75; TempCo: 100 ppm/C; EIA_Code: E96; U/M: EA
R150 = ERJ-3EKF4752V: RES, 47.5 k, 1%, 0.1 W, AEC-Q200 Grade 0, 0603; Manufacturer: Panasonic; CompType: Resistor; Value: 47.5k; Res_ohm: 47500; Value_Code: 47k5; Tolerance_%: 1; Power_W: 0.1; Value2: 0.1W; VDC_V: 50; TempCo: 100 ppm/C; SizeArea_mm2: 1.28; SizeX_mm: 1.6; SizeY_mm: 0.8; EIA_Code: E96; U/M: EA; AEC Category: Q200; AEC Qualified: Y; AEC Grade: 0; Green_Lifecycle: Active; Green_REACh: Passed
R152 = ERJ-8ENF3902V: RES, 39.0 k, 1%, 0.25 W, AEC-Q200 Grade 0, 1206; Manufacturer: Panasonic; CompType: Resistor; Value: 39.0k; Res_ohm: 39000; Value_Code: 39k0; Tolerance_%: 1; Power_W: 0.25; Value2: 0.25W; VDC_V: 200; TempCo: 100 ppm/C; SizeArea_mm2: 5.12; SizeX_mm: 3.2; SizeY_mm: 1.6; SizeZ_mm: 1.35; U/M: EA; AEC Category: Q200; AEC Qualified: Y; AEC Grade: 0
R153 = CRCW060316K5FKEA: RES, 16.5k ohm, 1%, 0.1W, 0603; Manufacturer: Vishay-Dale; CompType: Resistor; Res_ohm: 16500; Value_Code: 16k5; Tolerance_%: 1; Power_W: 0.1; VDC_V: 75; TempCo: 100 ppm/C; EIA_Code: E96; U/M: EA
R154 = CRCW06031K00JNEA: RES, 1.0 k, 5%, 0.1 W, 0603; Manufacturer: Vishay-Dale; CompType: Resistor; Value: 1.0k; Res_ohm: 1000; Value_Code: 1k00; Tolerance_%: 5; Power_W: 0.1; Value2: 0.1W; VDC_V: 75; TempCo: 200 ppm/C; EIA_Code: E24; U/M: EA
R156 = RC0603FR-072K49L: RES, 2.49 k, 1%, 0.1 W, 0603; Manufacturer: Yageo America; CompType: Resistor; Value: 2.49k; Res_ohm: 2490; Value_Code: 2k49; Tolerance_%: 1; Power_W: 0.1; Value2: 0.1W; VDC_V: 150; TempCo: 200 ppm/C; SizeArea_mm2: 1.28; SizeX_mm: 1.6; SizeY_mm: 0.8; EIA_Code: E96; U/M: EA; AEC Category: Q200; Green_Lifecycle: Active; Green_REACh: Passed
R159 = CRCW0603100KFKEA: RES, 100 k, 1%, 0.1 W, 0603; Manufacturer: Vishay-Dale; CompType: Resistor; Value: 100k; Res_ohm: 100000; Tolerance_%: 1; Power_W: 0.1; Value2: 0.1W; VDC_V: 75; TempCo: 100 ppm/C; EIA_Code: E96; U/M: EA
RT100 = B59751B0120A070: Thermistor NTC, 50 ohm, 25%, D12.5xH16.5mm; Manufacturer: TDK; Tolerance_%: 25; TaMin_C: -40; TaMax_C: 125; U/M: EA
SGND#1 = 5001: Test Point, Miniature, Black, TH; Manufacturer: Keystone; CompType: Test Point Loop; ContactFinish: Silver; Green_Lifecycle: Active; Green_REACh: Passed
SGND#2-SGND#4 = 5001: Test Point, Miniature, Black, TH; Manufacturer: Keystone; CompType: Test Point Loop; U/M: EA
T100 = CMP-0089702-1: 264W SMPS TRANSFORMER; Manufacturer: Payton Planar; PartNumber: 61201; TaMax_C: +40°C; Ns1toNp: 8:2:2; AEC Qualified: No; Voltage_Isolation_Vrms: 1500Vrms; TaMin_C: -20°C; SizeZ_mm: 17.5mm; Frequency_Fixed: 200-400kHz
T101 = CMP-0088854-1: 800uH DCM Flyback, 15V; Manufacturer: Renco; SizeZ_mm: 0.48inch; Ind_H: 800µH; DCR_ohm: 1.15; AEC Qualified: No; Voltage_Isolation_Vrms: 1.5kV; Ns1toNp: 1:0.226:0.194
U100 U101 = CMP-0013050-3: UCC24612-2DBV, DBV0005A (SOT-23-5); Manufacturer: Texas Instruments; Alternate PartNumber: UCC24612-2DBVT; SizeX_mm: 2.8; SizeY_mm: 2.9; CompType: IC; SizeZ_mm: 1.45; SizeArea_mm2: 8.12; SizeAreaWB_mm2: 14.82; AEC Category: Q200; AEC Qualified: N
U102 = UCC25630DDB: Enhanced LLC Resonant Controller with Driver, DDB0014A; Manufacturer: Texas Instruments; SymbolCreator: Altium; CompType: IC; U/M: EA
U103 = INA180A2IDBV: Low- and High-Side Measurement, Multichannel, Voltage Output, Current-Sense Amplifier, DBV0005A (SOT-5); Manufacturer: Texas Instruments; SymbolCreator: a0411947; SizeArea_mm2: 8.12; SizeAreaWB_mm2: 14.82; SizeX_mm: 2.8; SizeY_mm: 2.9; SizeZ_mm: 1.45; CompType: IC; U/M: EA
U104 = CMP-0068270-1: Low Power Quad Operational Amplifier, 14-pin Narrow SOIC; Manufacturer: Texas Instruments; CompType: Amplifiers; PackageTopMarking: NSUZXYTTE#*LM324M; PowerWise: N
U105 = CMP-0006187-2: OPTOISOLATOR 5.3KV TRANS 4-DIP; Manufacturer: Vishay-Semiconductor; PartNumber: VO618A-3; CTR (Max): 200%; SizeAreaWB_mm2: 71.064; CTR (Min): 100%; SizeZ_mm: 5; SizeX_mm: 8.8; SizeY_mm: 4.58; SizeArea_mm2: 40.304; CompType: Optocoupler
U106 = CMP-0067241-2: 700V Flyback Switcher with Constant-Voltage Constant-Current and Primary-side Control, D0007A (SOIC-7); Alternate Manufacturer: Texas Instruments; SizeAreaWB_mm2: 55.2; U/M: EA; SizeZ_mm: 1.75; SizeX_mm: 6.0; SizeY_mm: 4.9; SizeArea_mm2: 29.4; CompType: IC; AEC Category: Q200; AEC Qualified: N
U107 = LTV-817: Opto-Isolator, 1 Channel, TH; CompType: OPTOCOUPLER; U/M: EA

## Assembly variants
001: not fitted C105 C110 C136 C155 D102 D106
